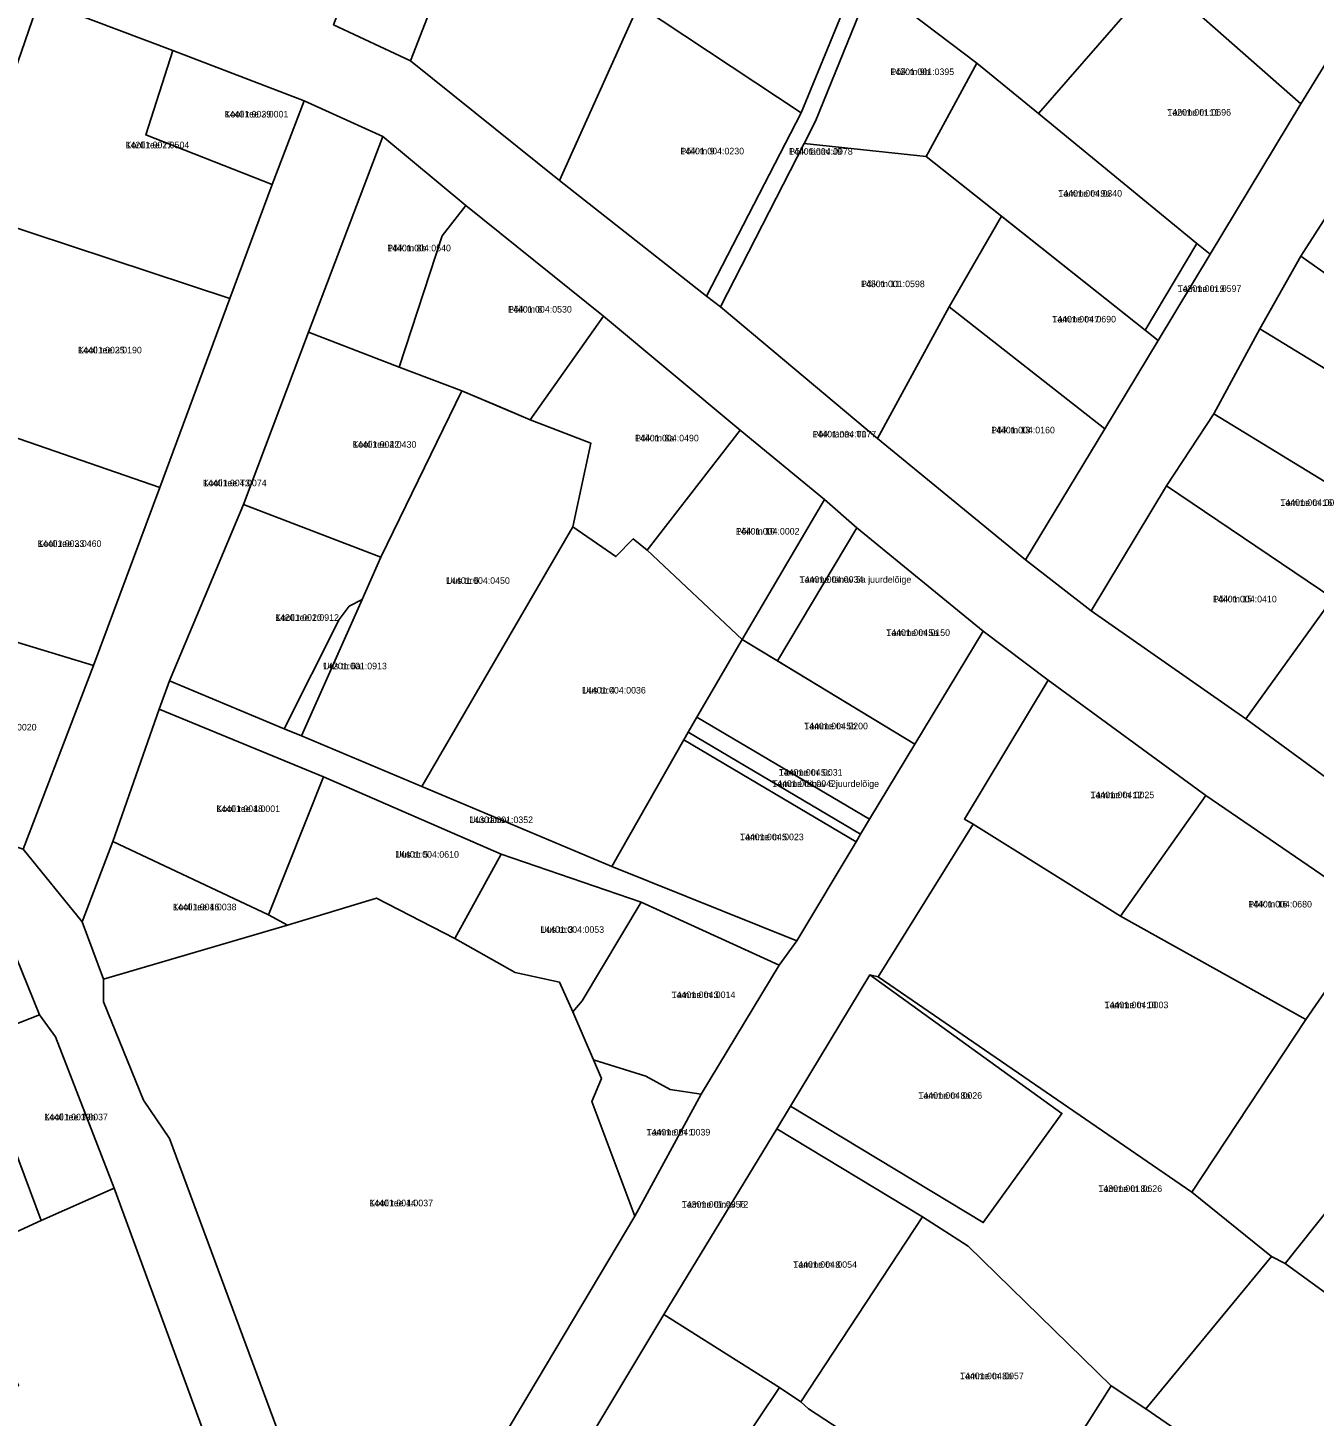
# Model space of a CAD drawing. Extents: x 640657 to 665127, y 6395726 to 6426831.
# Drawn here: x 650279.6 to 650572.3, y 6412794.8 to 6413110.9 of the extents above; entities that cross this region are included whole.
import ezdxf

# ---------------------------------------------------------------- set-up
doc = ezdxf.new("R2010")
doc.units = 0
for name, color, linetype in [('L_AADRESS', 7, 'Continuous'), ('PIIR', 7, 'Continuous'), ('TUNNUS', 7, 'Continuous')]:
    doc.layers.add(name, color=color, linetype=linetype)

msp = doc.modelspace()

# ---------------------------------------------------------------- linework, layer by layer
at = {"layer": 'PIIR'}
for points in [[(650447.93, 6413361.29), (650455.02, 6413332.18), (650450.1, 6413320), (650439.93, 6413292.9), (650427.74, 6413261.46), (650414.73, 6413228.41), (650413.5, 6413223.21), (650397.75, 6413184.5), (650387.68, 6413157.44), (650366.72, 6413103.36), (650349.21, 6413111.57), (650361.94, 6413144.67), (650378.35, 6413185.62), (650392.37, 6413223.71), (650406.97, 6413260.61), (650420.35, 6413295.13), (650432.57, 6413327.48)], [(650533.54, 6413170.85), (650539.77, 6413179.73), (650563.74, 6413161.57), (650555.61, 6413151.56), (650531.75, 6413126.74), (650536.61, 6413122.42), (650509.55, 6413091.33), (650495.52, 6413102.83), (650471.6, 6413121.03), (650491.92, 6413158.4), (650495.03, 6413162.84), (650510.82, 6413150.61), (650528.7, 6413174.65)], [(650387.68, 6413157.44), (650408.41, 6413149.51), (650402.81, 6413135.78), (650420.59, 6413120.53), (650418.55, 6413116), (650400.62, 6413076.11), (650366.72, 6413103.36)], [(650468.8, 6413123.7), (650455.57, 6413091.52), (650418.55, 6413116), (650420.59, 6413120.53), (650435.58, 6413154.3), (650444.55, 6413146.98)], [(650536.61, 6413122.42), (650531.75, 6413126.74), (650555.61, 6413151.56), (650587.57, 6413123.41), (650569.27, 6413093.53)], [(650217.56, 6413097.01), (650231.92, 6413140.01), (650283.94, 6413122.19), (650282.18, 6413117.13), (650268.45, 6413077.48), (650237.31, 6413088.1)], [(650468.8, 6413123.7), (650471.6, 6413121.03), (650458.86, 6413089.63), (650456.25, 6413084.52), (650437.23, 6413047.33), (650434.02, 6413049.75), (650455.57, 6413091.52)], [(650471.6, 6413121.03), (650495.52, 6413102.83), (650484.02, 6413081.59), (650456.25, 6413084.52), (650458.86, 6413089.63)], [(650509.55, 6413091.33), (650536.61, 6413122.42), (650569.27, 6413093.53), (650548.62, 6413059.33), (650545.59, 6413061.79)], [(650282.18, 6413117.13), (650312.64, 6413105.72), (650306.45, 6413086.49), (650335.26, 6413075.19), (650325.62, 6413049.27), (650271.11, 6413067.27), (650268.45, 6413077.48)], [(650418.55, 6413116), (650455.57, 6413091.52), (650434.02, 6413049.75), (650400.62, 6413076.11)], [(650312.64, 6413105.72), (650342.53, 6413094.26), (650335.26, 6413075.19), (650306.45, 6413086.49)], [(650545.59, 6413061.79), (650533.87, 6413042.03), (650484.02, 6413081.59), (650495.52, 6413102.83), (650509.55, 6413091.33)], [(650342.53, 6413094.26), (650360.4, 6413086.12), (650343.5, 6413041.6), (650328.69, 6413002.34), (650311.89, 6412962.22), (650309.49, 6412955.73), (650298.99, 6412925.64), (650292.03, 6412907.35), (650278.55, 6412923.91), (650294.57, 6412965.73), (650309.67, 6413006.23), (650325.62, 6413049.27), (650335.26, 6413075.19)], [(650360.4, 6413086.12), (650379.29, 6413070.42), (650373.9, 6413063.5), (650364.1, 6413033.65), (650343.5, 6413041.6)], [(650437.23, 6413047.33), (650456.25, 6413084.52), (650484.02, 6413081.59), (650501.18, 6413067.96), (650489.24, 6413047.34), (650472.97, 6413017.35)], [(650582.29, 6413079.22), (650615.55, 6413054.42), (650621.57, 6413049.93), (650614.85, 6413040.56), (650607.93, 6413032.74), (650605.2, 6413033.45), (650569.28, 6413058.87)], [(650364.1, 6413033.65), (650373.9, 6413063.5), (650379.29, 6413070.42), (650410.61, 6413045.25), (650393.91, 6413021.66), (650378.37, 6413028.26)], [(650271.11, 6413067.27), (650325.62, 6413049.27), (650309.67, 6413006.23), (650269.73, 6413020.05), (650257.13, 6413024.41), (650260.59, 6413035.01)], [(650536.83, 6413039.67), (650524.64, 6413019.61), (650489.24, 6413047.34), (650501.18, 6413067.96), (650533.87, 6413042.03)], [(650536.83, 6413039.67), (650533.87, 6413042.03), (650545.59, 6413061.79), (650548.62, 6413059.33)], [(650559.96, 6413042.34), (650569.28, 6413058.87), (650605.2, 6413033.45), (650607.93, 6413032.74), (650600.92, 6413017.32)], [(650413.45, 6412990.5), (650403.66, 6412997.26), (650407.73, 6413016.29), (650393.91, 6413021.66), (650410.61, 6413045.25), (650441.68, 6413019.24), (650420.52, 6412991.93), (650417.38, 6412994.56)], [(650506.59, 6412989.76), (650472.97, 6413017.35), (650489.24, 6413047.34), (650524.64, 6413019.61)], [(650328.69, 6413002.34), (650343.5, 6413041.6), (650364.1, 6413033.65), (650378.37, 6413028.26), (650359.94, 6412990.38)], [(650559.96, 6413042.34), (650600.92, 6413017.32), (650599.7, 6413014.64), (650597.83, 6413011.87), (650588.87, 6412998.92), (650549.45, 6413023.01)], [(650359.94, 6412990.38), (650378.37, 6413028.26), (650388.49, 6413023.96), (650393.91, 6413021.66), (650407.73, 6413016.29), (650403.66, 6412997.26), (650369.27, 6412938.14), (650341.88, 6412949.67), (650355.67, 6412980.76)], [(650538.74, 6413006.57), (650549.45, 6413023.01), (650588.87, 6412998.92), (650576.52, 6412981.06)], [(650254.08, 6412977.96), (650269.73, 6413020.05), (650309.67, 6413006.23), (650294.57, 6412965.73)], [(650441.68, 6413019.24), (650460.89, 6413003.46), (650442.19, 6412971.64), (650420.52, 6412991.93)], [(650575.99, 6412939.48), (650556.73, 6412953.59), (650576.52, 6412981.06), (650588.87, 6412998.92), (650597.83, 6413011.87), (650616.29, 6412992.52), (650601.13, 6412971.82), (650598.5, 6412973.02), (650587.24, 6412956.25)], [(650538.74, 6413006.57), (650576.52, 6412981.06), (650556.73, 6412953.59), (650521.58, 6412978.11)], [(650311.89, 6412962.22), (650328.69, 6413002.34), (650359.94, 6412990.38), (650355.67, 6412980.76), (650352.71, 6412979.18), (650350.5, 6412976.16), (650337.96, 6412951.3)], [(650460.89, 6413003.46), (650468.26, 6412997.06), (650450.18, 6412966.79), (650442.19, 6412971.64)], [(650403.66, 6412997.26), (650413.45, 6412990.5), (650417.38, 6412994.56), (650420.52, 6412991.93), (650442.19, 6412971.64), (650431.87, 6412953.95), (650429.87, 6412950.54), (650428.9, 6412948.81), (650412.49, 6412919.96), (650369.27, 6412938.14)], [(650468.26, 6412997.06), (650496.99, 6412973.51), (650481.47, 6412947.83), (650450.18, 6412966.79)], [(650352.71, 6412979.18), (650355.67, 6412980.76), (650341.88, 6412949.67), (650337.96, 6412951.3), (650350.5, 6412976.16)], [(650249.29, 6412964.7), (650254.08, 6412977.96), (650294.57, 6412965.73), (650278.55, 6412923.91), (650239.67, 6412937.15)], [(650442.19, 6412971.64), (650481.47, 6412947.83), (650471.14, 6412930.69), (650431.87, 6412953.95)], [(650346.93, 6412940.38), (650309.49, 6412955.73), (650311.89, 6412962.22), (650337.96, 6412951.3), (650341.88, 6412949.67), (650369.27, 6412938.14), (650412.49, 6412919.96), (650454.63, 6412903.06), (650450.58, 6412897.45), (650419.21, 6412911.85), (650387.33, 6412922.79)], [(650547.67, 6412936.14), (650528.27, 6412908.65), (650494.73, 6412929.57), (650492.74, 6412930.74), (650511.76, 6412962.35)], [(650298.99, 6412925.64), (650309.49, 6412955.73), (650346.93, 6412940.38), (650334.37, 6412908.95)], [(650431.87, 6412953.95), (650471.14, 6412930.69), (650469.12, 6412927.28), (650429.87, 6412950.54)], [(650429.87, 6412950.54), (650469.12, 6412927.28), (650468.08, 6412925.56), (650428.9, 6412948.81)], [(650412.49, 6412919.96), (650428.9, 6412948.81), (650468.08, 6412925.56), (650454.63, 6412903.06)], [(650387.33, 6412922.79), (650376.75, 6412903.52), (650358.95, 6412912.76), (650338.71, 6412906.62), (650334.37, 6412908.95), (650346.93, 6412940.38)], [(650587.03, 6412909.19), (650570.41, 6412885.11), (650528.27, 6412908.65), (650547.67, 6412936.14)], [(650494.73, 6412929.57), (650528.27, 6412908.65), (650570.41, 6412885.11), (650544.44, 6412845.81), (650473.1, 6412894.8)], [(650296.86, 6412894.32), (650292.03, 6412907.35), (650298.99, 6412925.64), (650334.37, 6412908.95), (650338.71, 6412906.62)], [(650387.33, 6412922.79), (650419.21, 6412911.85), (650405.75, 6412889.33), (650403.65, 6412886.89), (650400.6, 6412893.6), (650390.5, 6412895.83), (650376.75, 6412903.52)], [(650417.77, 6412840.38), (650383.45, 6412782.73), (650345.05, 6412768.31), (650311.87, 6412858.01), (650305.95, 6412866.72), (650296.86, 6412889.11), (650296.86, 6412894.32), (650338.71, 6412906.62), (650358.95, 6412912.76), (650376.75, 6412903.52), (650390.5, 6412895.83), (650400.6, 6412893.6), (650403.65, 6412886.89), (650408.31, 6412875.93), (650410.14, 6412871.67), (650407.97, 6412866.46)], [(650210.67, 6412800.52), (650208.07, 6412813.16), (650204.13, 6412822.35), (650201.08, 6412831.03), (650197.94, 6412840.41), (650187.12, 6412872.57), (650272.9, 6412909.24), (650282.26, 6412886.17), (650267.38, 6412880.34), (650282.69, 6412839.36), (650264.5, 6412831.05), (650245.1, 6412820.91), (650237.85, 6412816.79), (650224.05, 6412807.61)], [(650419.21, 6412911.85), (650450.58, 6412897.45), (650432.85, 6412868.13), (650425.76, 6412869.21), (650420.27, 6412872.25), (650408.31, 6412875.93), (650403.65, 6412886.89), (650405.75, 6412889.33)], [(650587.03, 6412909.19), (650613.3, 6412891.26), (650596.19, 6412868.66), (650582.65, 6412850.8), (650565.69, 6412829.54), (650562.63, 6412831.16), (650544.44, 6412845.81), (650570.41, 6412885.11)], [(650471.24, 6412895.26), (650473.1, 6412894.8), (650544.44, 6412845.81), (650562.63, 6412831.16), (650534.02, 6412796.48), (650526.12, 6412801.71), (650493.55, 6412833.51), (650483.2, 6412840.21), (650450.02, 6412860.21), (650453.14, 6412865.36), (650497.03, 6412838.88), (650514.92, 6412863.75)], [(650471.24, 6412895.26), (650514.92, 6412863.75), (650497.03, 6412838.88), (650453.14, 6412865.36)], [(650267.38, 6412880.34), (650282.26, 6412886.17), (650285.9, 6412881.2), (650299.3, 6412846.7), (650282.69, 6412839.36)], [(650417.77, 6412840.38), (650407.97, 6412866.46), (650410.14, 6412871.67), (650408.31, 6412875.93), (650420.27, 6412872.25), (650425.76, 6412869.21), (650432.85, 6412868.13)], [(650424.35, 6412817.94), (650450.02, 6412860.21), (650483.2, 6412840.21), (650455.48, 6412798.05), (650450.69, 6412801.37)], [(650582.65, 6412850.8), (650628.07, 6412817.98), (650611.45, 6412796.26), (650565.69, 6412829.54)], [(650208.51, 6412773.92), (650218.79, 6412778), (650277.53, 6412801.82), (650264.5, 6412831.05), (650282.69, 6412839.36), (650299.3, 6412846.7), (650329.8, 6412763.6), (650227.2, 6412726.23), (650217.94, 6412750.3)], [(650455.48, 6412798.05), (650483.2, 6412840.21), (650493.55, 6412833.51), (650526.12, 6412801.71), (650503.6, 6412766.24), (650457.28, 6412796.49)], [(650534.02, 6412796.48), (650562.63, 6412831.16), (650565.69, 6412829.54), (650611.45, 6412796.26), (650584.65, 6412761.55)], [(650427.29, 6412766.46), (650402.06, 6412780.76), (650424.35, 6412817.94), (650450.69, 6412801.37), (650436.3, 6412779.95)], [(650450.69, 6412801.37), (650455.48, 6412798.05), (650457.28, 6412796.49), (650503.6, 6412766.24), (650515.2, 6412759.31), (650491.34, 6412719.91), (650484.11, 6412724.36), (650436.06, 6412749.03), (650441.14, 6412758.16), (650442.52, 6412759.16), (650436.3, 6412779.95)], [(650559.55, 6412729.99), (650515.2, 6412759.31), (650503.6, 6412766.24), (650526.12, 6412801.71), (650534.02, 6412796.48), (650584.65, 6412761.55)]]:
    msp.add_lwpolyline(points, close=True, dxfattribs=at)
for points in [[(650619.58, 6413139.45), (650599.89, 6413108.8), (650582.29, 6413079.22), (650569.28, 6413058.87), (650559.96, 6413042.34), (650549.45, 6413023.01), (650538.74, 6413006.57), (650521.58, 6412978.11), (650506.59, 6412989.76), (650524.64, 6413019.61), (650536.83, 6413039.67), (650548.62, 6413059.33), (650569.27, 6413093.53), (650587.57, 6413123.41)], [(650587.03, 6412909.19), (650547.67, 6412936.14), (650511.76, 6412962.35), (650496.99, 6412973.51), (650468.26, 6412997.06), (650460.89, 6413003.46), (650441.68, 6413019.24), (650410.61, 6413045.25), (650379.29, 6413070.42), (650360.4, 6413086.12), (650342.53, 6413094.26), (650312.64, 6413105.72), (650282.18, 6413117.13)], [(650349.21, 6413111.57), (650366.72, 6413103.36), (650400.62, 6413076.11), (650434.02, 6413049.75), (650437.23, 6413047.33), (650472.97, 6413017.35), (650506.59, 6412989.76), (650521.58, 6412978.11), (650556.73, 6412953.59), (650575.99, 6412939.48)], [(650383.45, 6412782.73), (650417.77, 6412840.38), (650432.85, 6412868.13), (650450.58, 6412897.45), (650454.63, 6412903.06), (650468.08, 6412925.56), (650469.12, 6412927.28), (650471.14, 6412930.69), (650481.47, 6412947.83), (650496.99, 6412973.51), (650511.76, 6412962.35), (650492.74, 6412930.74), (650494.73, 6412929.57), (650473.1, 6412894.8), (650471.24, 6412895.26), (650453.14, 6412865.36), (650450.02, 6412860.21), (650424.35, 6412817.94), (650402.06, 6412780.76)], [(650278.55, 6412923.91), (650292.03, 6412907.35), (650296.86, 6412894.32), (650296.86, 6412889.11), (650305.95, 6412866.72), (650311.87, 6412858.01), (650345.05, 6412768.31), (650352.3, 6412752.69), (650374.32, 6412694.32), (650388.11, 6412657.18), (650401.68, 6412620.02)], [(650386.32, 6412614.06), (650375.93, 6412640.11), (650361.5, 6412679.88), (650357.8, 6412690.63), (650351.84, 6412704.65), (650343.32, 6412727.61), (650344.83, 6412728.23), (650339.2, 6412743.9), (650337.4, 6412743.2), (650329.8, 6412763.6), (650299.3, 6412846.7), (650285.9, 6412881.2), (650282.26, 6412886.17), (650272.9, 6412909.24)]]:
    msp.add_lwpolyline(points, dxfattribs=at)

# ---------------------------------------------------------------- texts
at = {"layer": 'L_AADRESS'}
for s, p in [('Põik tn 9b', (650475.89, 6413100.11)), ('Tamme tn 11', (650538.89, 6413090.88)), ('Kooli tee 29', (650324.4, 6413090.46)), ('Kooli tee 27', (650301.86, 6413083.44)), ('Põik tn 9', (650428.09, 6413082.06)), ('Põik tänav J9', (650452.81, 6413081.98)), ('Tamme tn 9a', (650514.09, 6413072.43)), ('Põik tn 8b', (650361.39, 6413059.99)), ('Põik tn 11', (650469.2, 6413051.83)), ('Tamme tn 9', (650541.24, 6413050.75)), ('Põik tn 8', (650388.9, 6413046.04)), ('Tamme tn 7', (650512.72, 6413043.79)), ('Kooli tee 25', (650291.07, 6413036.75)), ('Põik tn 13', (650498.81, 6413018.55)), ('Kooli tee 22', (650353.53, 6413015.28)), ('Põik tn 8a', (650417.79, 6413016.72)), ('Põik tänav T1', (650458.16, 6413017.62)), ('Kooli tee T3', (650319.47, 6413006.51)), ('Tamme tn 16', (650564.61, 6413002.04)), ('Kooli tee 23', (650281.88, 6412992.71)), ('Põik tn 10', (650440.71, 6412995.51)), ('Uus tn 6', (650374.8, 6412984.29)), ('Tamme tänav 5a juurdelõige', (650455.22, 6412984.53)), ('Põik tn 15', (650549.29, 6412980.08)), ('Kooli tee 20', (650335.91, 6412975.87)), ('Tamme tn 5a', (650474.95, 6412972.44)), ('Uus tn 6a', (650346.82, 6412964.83)), ('Uus tn 4', (650405.73, 6412959.32)), ('Tamme tn 5b', (650456.27, 6412951.17)), ('Tamme tn 5c', (650450.5, 6412940.62)), ('Tamme tänav 5 juurdelõige', (650448.99, 6412938.05)), ('Tamme tn 12', (650521.41, 6412935.5)), ('Kooli tee 18', (650322.52, 6412932.34)), ('Uus tänav', (650380.08, 6412929.83)), ('Tamme tn 5', (650441.67, 6412925.93)), ('Uus tn 5', (650363.22, 6412921.95)), ('Põik tn 16', (650557.3, 6412910.62)), ('Kooli tee 16', (650312.61, 6412909.98)), ('Uus tn 3', (650396.25, 6412904.84)), ('Tamme tn 3', (650426.11, 6412889.99)), ('Tamme tn 10', (650524.62, 6412887.69)), ('Tamme tn 8a', (650482.25, 6412867.07)), ('Kooli tee 19b', (650283.34, 6412862.17)), ('Tamme tn 1', (650420.41, 6412858.71)), ('Tamme tn 8c', (650523.21, 6412845.87)), ('Kooli tee 14', (650357.32, 6412842.59)), ('Tamme tänav T2', (650428.4, 6412842.28)), ('Tamme tn 8', (650453.78, 6412828.59)), ('Tamme tn 8b', (650491.73, 6412803.23))]:
    msp.add_text(s, height=1.5, dxfattribs=at).set_placement(p)
at = {"layer": 'TUNNUS'}
for s, p in [('14201:001:0395', (650475.89, 6413100.11)), ('14201:001:0696', (650538.89, 6413090.88)), ('14401:003:0001', (650324.4, 6413090.46)), ('14201:001:0504', (650301.86, 6413083.44)), ('14401:004:0230', (650428.09, 6413082.06)), ('14401:004:0078', (650452.81, 6413081.98)), ('14401:004:0340', (650514.09, 6413072.43)), ('14401:004:0540', (650361.39, 6413059.99)), ('14301:001:0598', (650469.2, 6413051.83)), ('14201:001:0597', (650541.24, 6413050.75)), ('14401:004:0530', (650388.9, 6413046.04)), ('14401:004:0690', (650512.72, 6413043.79)), ('14401:003:0190', (650291.07, 6413036.75)), ('14401:004:0160', (650498.81, 6413018.55)), ('14401:004:0430', (650353.53, 6413015.28)), ('14401:004:0490', (650417.79, 6413016.72)), ('14401:004:0077', (650458.16, 6413017.62)), ('14401:004:0074', (650319.47, 6413006.51)), ('14401:004:0005', (650564.61, 6413002.04)), ('14401:003:0460', (650281.88, 6412992.71)), ('14401:004:0002', (650440.71, 6412995.51)), ('14401:004:0450', (650374.8, 6412984.29)), ('14401:004:0034', (650455.22, 6412984.53)), ('14401:004:0410', (650549.29, 6412980.08)), ('14201:001:0912', (650335.91, 6412975.87)), ('14401:004:0150', (650474.95, 6412972.44)), ('14201:001:0913', (650346.82, 6412964.83)), ('14401:004:0036', (650405.73, 6412959.32)), ('14401:003:0020', (650267.12, 6412950.91)), ('14401:004:0200', (650456.27, 6412951.17)), ('14401:004:0031', (650450.5, 6412940.62)), ('14401:004:0042', (650448.99, 6412938.05)), ('14401:004:0025', (650521.41, 6412935.5)), ('14401:004:0001', (650322.52, 6412932.34)), ('14301:001:0352', (650380.08, 6412929.83)), ('14401:004:0023', (650441.67, 6412925.93)), ('14401:004:0610', (650363.22, 6412921.95)), ('14401:004:0680', (650557.3, 6412910.62)), ('14401:004:0038', (650312.61, 6412909.98)), ('14401:004:0053', (650396.25, 6412904.84)), ('14401:004:0014', (650426.11, 6412889.99)), ('14401:004:0003', (650524.62, 6412887.69)), ('14401:004:0026', (650482.25, 6412867.07)), ('14401:003:0037', (650283.34, 6412862.17)), ('14401:004:0039', (650420.41, 6412858.71)), ('14301:001:0626', (650523.21, 6412845.87)), ('14401:004:0037', (650357.32, 6412842.59)), ('14301:001:0356', (650428.4, 6412842.28)), ('14401:004:0054', (650453.78, 6412828.59)), ('14401:004:0057', (650491.73, 6412803.23))]:
    msp.add_text(s, height=1.5, dxfattribs=at).set_placement(p)

doc.saveas('drawing.dxf')
